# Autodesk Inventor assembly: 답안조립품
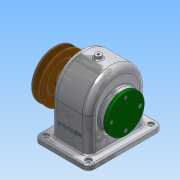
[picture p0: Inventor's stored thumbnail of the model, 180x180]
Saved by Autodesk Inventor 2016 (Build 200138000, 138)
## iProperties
Created: 2018-08
Part Number: 답안조립품
Material: 일반
Document SubType Name: Assembly
Designer: Administrator
Author: Administrator
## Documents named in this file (13)
- C:\Users\Administrator\Desktop\480811V1005\답안조립품.iam
- C:\Users\Administrator\Desktop\480811V1005\본체.ipt
- C:\Users\Administrator\Desktop\480811V1005\베어링 6203.ipt
- C:\Users\Administrator\Desktop\480811V1005\뒤커버.ipt
- C:\Users\Administrator\Desktop\480811V1005\앞커버.ipt
- C:\Users\Administrator\Desktop\480811V1005\볼트 M4.ipt
- C:\Users\Administrator\Desktop\480811V1005\축.ipt
- C:\Users\Administrator\Desktop\480811V1005\스퍼기어.ipt
- C:\Users\Administrator\Desktop\480811V1005\키 6x6x22.ipt
- C:\Users\Administrator\Desktop\480811V1005\오일 실 28 40 8.ipt
- C:\Users\Administrator\Desktop\480811V1005\키 5x5x18.ipt
- C:\Users\Administrator\Desktop\480811V1005\V-벨트풀리.ipt
- C:\Users\Administrator\Desktop\480811V1005\멈춤나사 M4.ipt
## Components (1 placed, 1 different names)
1. V-벨트풀리:1
